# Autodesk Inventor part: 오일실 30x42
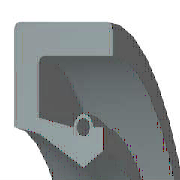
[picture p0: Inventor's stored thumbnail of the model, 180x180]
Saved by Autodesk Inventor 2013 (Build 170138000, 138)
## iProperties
IsCustomPart: 0
Company: 한국ATC센터
Created: 2009-02
Part Number: 오일실 30x42
Material: 고무
Description: 오일-실
Document SubType Name: Modeling
Standard: KS B 2804
Designer: KYOUNG IL JANG
Standards Organization: KS
Language: ko-KR
Size Designation: S - 30 42 8
Categories: <MemberInstance><Categories><Category DisplayName="샤프트 부품" InternalName="7f7aeb1f-a693-4053-b835-cee3144e0d98" Mnemonic="SHFT"><Category DisplayName="실링" Intern
Density: 0.93 g/cm^3
Author: KYOUNG IL JANG
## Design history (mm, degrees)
revolve "본체" stored, may be unused: angle "d17" = 90 deg
revolve "스프링1" stored, may be unused: angle "d18" = 90 deg
body "Solid1"
sketch "스케치1"
  geometry: L1 (0, 21)-(8, 21); L2 (8, 21)-(8, 19.75); L3 (8, 19.75)-(1.75, 19.75); L4 (0, 21)-(0, 17.1); L5 (0, 17.1)-(1.75, 16.75); L6 (1.75, 16.75)-(4.9, 15); L7 (4.9, 15)-(0, 15); L8 (6.3, 15.875)-(6.3, 17.1); L9 (0, 0)-(9.586, 0) reference; L10 (4.9, 15)-(6.3, 15.875); L11 (0, 18)-(0, -3) reference; L12 (-1.917, 0)-(11.503, 0) reference; L13 (4.2, 17.1)-(1.75, 17.59); L14 (1.75, 17.59)-(1.75, 19.75); L15 (6.3, 17.1)-(5.6, 17.1); C1 r 0.455 at (4.9, 17.1); A1 r 0.7 centre (4.9, 17.1) between (5.6, 17.1) and (4.2, 17.1)
  constraints: 26 end point, 5 horizontal alignment, 4 perpendicular, 2 centre point, 2 collinear, 2 horizontal, 2 parallel, 2 point on circle, 2 point on line, 2 vertical alignment, 1 coincident
  dimensions: "d0" = 42 diameter of L1 L9 (= SD2); "d1" = 31.75 diameter of L8.start L9 (= ABDM); "d2" = 1.25 distance of L1.end L2.end (computed from SD); "d3" = 0.91 diameter of C1 (= SPDI); "d4" = 1.4 diameter of A1 (= SPDA); "d5" = 30 diameter of L6.end L9 (= NND); "d6" = 33.5 diameter of L5.end L9 (= TKDM); "d7" = 34.2 diameter of L4.end L9 (= HLDM); "d8" = 4.9 distance from line of C1.centre L4 (= SPDST); "d9" = 6.3 distance between parallel lines of L8 L4 (= SDI); "d10" = 8 distance between parallel lines of L2 L4 (= SWDT); "d12" = 1.75 distance between parallel lines of L14 L4 (= SD)
fillet "모깎기1" dims "d11" = 0.4 (= RR)
other parameters: "SD2" = 42 [user parameter; used in 1 equation term], "SWDT" = 8 [user parameter; used in 1 equation term], "RR" = 0.4 [user parameter; used in 1 equation term], "SD" = 1.75 [user parameter; used in 2 equation terms], "NND" = 30 [user parameter; used in 1 equation term], "SPDA" = 1.4 [user parameter; used in 1 equation term], "SPDI" = 0.91 [user parameter; used in 1 equation term], "TKDM" = 33.5 [user parameter; used in 1 equation term], "HLDM" = 34.2 [user parameter; used in 1 equation term], "ABDM" = 31.75 [user parameter; used in 1 equation term], "SDI" = 6.3 [user parameter; used in 1 equation term], "SPDST" = 4.9 [user parameter; used in 1 equation term], "d13" = 0, "d14" = 0, "d15" = 0, "LAB" = 0.35 [user parameter]
